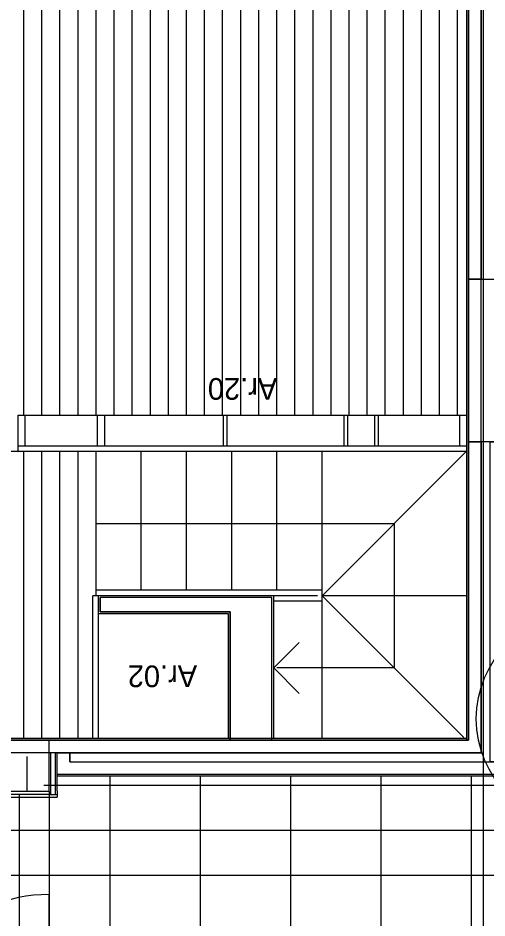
# Model space of a CAD drawing. Extents: x 1248 to 1356, y -443 to -224.
# Drawn here: x 1337.511 to 1340.106, y -239.409 to -234.424 of the extents above; entities that cross this region are included whole.
import ezdxf

# ---------------------------------------------------------------- set-up
doc = ezdxf.new("R2010")
doc.units = 0
for name, color, linetype in [('corte', 7, 'Continuous'), ('estereoctomias', 7, 'Continuous'), ('ind-pormenores', 7, 'Continuous'), ('Level 1', 7, 'Continuous'), ('Level 10', 7, 'Continuous'), ('Level 13', 7, 'Continuous'), ('Level 2', 7, 'Continuous'), ('Level 4', 7, 'Continuous'), ('Level 40', 7, 'Continuous'), ('revestimentos', 7, 'Continuous'), ('vermelhos-cont', 7, 'Continuous')]:
    doc.layers.add(name, color=color, linetype=linetype)

msp = doc.modelspace()

# ---------------------------------------------------------------- linework, layer by layer
at = {"layer": 'corte'}
for p, q in [((1340.0033, -238.424), (1340.0033, -232.264)), ((1340.0733, -236.7713), (1340.0733, -232.264)), ((1340.0733, -238.494), (1340.0733, -236.7713)), ((1340.0033, -238.424), (1336.8183, -238.424)), ((1337.7983, -238.494), (1340.0733, -238.494)), ((1337.7983, -238.544), (1341.234, -238.544)), ((1341.339, -238.614), (1337.7283, -238.614))]:
    msp.add_line(p, q, dxfattribs=at)
msp.add_lwpolyline([(1340.0033, -235.8713), (1340.2333, -235.8713), (1340.2333, -236.7713), (1340.0033, -236.7713)], close=True, dxfattribs=at)
at = {"layer": 'estereoctomias'}
for points in [[(1340.0733, -232.264), (1340.0733, -235.8713), (1340.0033, -235.8713), (1340.0033, -232.264)], [(1340.0733, -236.7713), (1340.0733, -238.4784), (1340.0733, -238.494), (1336.8883, -238.494), (1336.8883, -238.709), (1336.8183, -238.709), (1336.8183, -238.424), (1340.0033, -238.424), (1340.0033, -236.7713)], [(1341.339, -238.424), (1341.339, -238.614), (1337.7283, -238.614), (1337.7283, -238.544), (1337.7283, -238.494), (1337.7983, -238.494), (1337.7983, -238.544), (1341.234, -238.544), (1341.234, -238.244), (1340.804, -238.244), (1340.804, -238.544), (1340.774, -238.544), (1340.774, -238.244), (1340.234, -238.244), (1340.234, -238.544), (1340.124, -238.544), (1340.124, -236.7713), (1340.234, -236.7713), (1340.234, -238.094), (1341.154, -238.094), (1341.154, -237.584), (1341.304, -237.584), (1341.304, -238.424)], [(1338.9158, -238.424), (1338.9158, -237.634), (1337.9658, -237.634), (1337.9658, -237.714), (1338.6858, -237.714), (1338.6858, -238.424)]]:
    msp.add_lwpolyline(points, close=True, dxfattribs=at)
at = {"layer": 'ind-pormenores'}
msp.add_circle((1340.6308, -238.3059), 0.5842, dxfattribs=at)
at = {"layer": 'Level 1'}
for p, q in [((1340.0033, -232.264), (1340.0033, -238.424)), ((1337.9658, -237.714), (1337.9658, -237.634)), ((1338.9158, -237.634), (1337.9658, -237.634)), ((1338.9158, -238.424), (1338.9158, -237.634)), ((1338.6858, -237.714), (1337.9658, -237.714)), ((1338.6858, -238.424), (1338.6858, -237.714)), ((1337.7283, -238.494), (1336.8883, -238.494)), ((1337.7283, -238.614), (1337.7283, -238.494)), ((1337.7983, -238.544), (1337.7983, -238.494))]:
    msp.add_line(p, q, dxfattribs=at)
at = {"layer": 'Level 10'}
for p, q in [((1337.5433, -236.624), (1337.5433, -232.274)), ((1337.6433, -236.624), (1337.6433, -232.274)), ((1337.7433, -236.624), (1337.7433, -232.274)), ((1337.8433, -236.624), (1337.8433, -232.274)), ((1337.9433, -236.624), (1337.9433, -232.274)), ((1338.0433, -236.624), (1338.0433, -232.274)), ((1338.1433, -236.624), (1338.1433, -232.274)), ((1338.2433, -236.624), (1338.2433, -232.274)), ((1338.3433, -236.624), (1338.3433, -232.274)), ((1338.4433, -236.624), (1338.4433, -232.274)), ((1338.5433, -236.624), (1338.5433, -232.274)), ((1338.6433, -236.624), (1338.6433, -232.274)), ((1338.7433, -236.624), (1338.7433, -232.274)), ((1338.8433, -236.624), (1338.8433, -232.274)), ((1338.9433, -236.624), (1338.9433, -232.274)), ((1339.0433, -236.624), (1339.0433, -232.274)), ((1339.1433, -236.624), (1339.1433, -232.274)), ((1339.2433, -236.624), (1339.2433, -232.274)), ((1339.3433, -236.624), (1339.3433, -232.274)), ((1339.4433, -236.624), (1339.4433, -232.274)), ((1339.5433, -236.624), (1339.5433, -232.274)), ((1339.6433, -236.624), (1339.6433, -232.274)), ((1339.7433, -236.624), (1339.7433, -232.274)), ((1339.8433, -236.624), (1339.8433, -232.274)), ((1339.9433, -236.624), (1339.9433, -232.274)), ((1337.5433, -238.409), (1337.5433, -236.824)), ((1337.6433, -238.409), (1337.6433, -236.824)), ((1337.7433, -238.409), (1337.7433, -236.824)), ((1337.8433, -238.409), (1337.8433, -236.824)), ((1338.0183, -238.624), (1338.0183, -240.224)), ((1338.5183, -238.624), (1338.5183, -240.224)), ((1339.0183, -238.624), (1339.0183, -240.224)), ((1339.5183, -238.624), (1339.5183, -240.224)), ((1340.0183, -238.624), (1340.0183, -240.224)), ((1337.6533, -238.674), (1341.274, -238.674)), ((1337.5183, -238.724), (1337.5183, -240.124)), ((1348.9433, -238.924), (1315.7644, -238.924)), ((1347.9933, -239.174), (1315.7633, -239.174))]:
    msp.add_line(p, q, dxfattribs=at)
at = {"layer": 'Level 13'}
for p, q in [((1337.5113, -236.824), (1337.5113, -236.624)), ((1337.5113, -236.624), (1339.9933, -236.624)), ((1337.5513, -236.794), (1337.5513, -236.624)), ((1337.9513, -236.794), (1337.9513, -236.624)), ((1337.9913, -236.794), (1337.9913, -236.624)), ((1338.6486, -236.794), (1338.6486, -236.624)), ((1338.6686, -236.794), (1338.6686, -236.624)), ((1339.3159, -236.794), (1339.3159, -236.624)), ((1339.3359, -236.794), (1339.3359, -236.624)), ((1339.4859, -236.794), (1339.4859, -236.624)), ((1339.5059, -236.794), (1339.5059, -236.624)), ((1339.9533, -236.624), (1339.9533, -236.794)), ((1337.5113, -236.794), (1339.9933, -236.794)), ((1337.5113, -236.824), (1339.9933, -236.824)), ((1337.5113, -236.824), (1339.9933, -236.824)), ((1337.5113, -236.824), (1339.9933, -236.824)), ((1337.9398, -236.824), (1339.9933, -236.824)), ((1337.9258, -238.414), (1337.9258, -237.624)), ((1337.9558, -237.624), (1337.9258, -237.624)), ((1337.9733, -237.624), (1337.9433, -237.624)), ((1337.9558, -238.414), (1337.9558, -237.624)), ((1337.6833, -238.709), (1337.6833, -238.494)), ((1337.6933, -238.724), (1337.6933, -238.494)), ((1337.7183, -238.724), (1337.7183, -238.494)), ((1337.7283, -238.704), (1337.7283, -238.614)), ((1337.6833, -238.709), (1336.7783, -238.709)), ((1337.6833, -238.724), (1336.8183, -238.724)), ((1337.6833, -238.724), (1336.8183, -238.724)), ((1337.6833, -238.724), (1336.8283, -238.724)), ((1337.6833, -238.709), (1337.6833, -238.724)), ((1337.6833, -238.724), (1337.6833, -238.739)), ((1337.6833, -238.724), (1337.7283, -238.724)), ((1337.7283, -238.704), (1337.7283, -238.724)), ((1337.7283, -238.724), (1337.7283, -238.739)), ((1337.6833, -238.739), (1337.7283, -238.739))]:
    msp.add_line(p, q, dxfattribs=at)
at = {"layer": 'Level 2'}
for p, q in [((1337.9433, -237.624), (1337.9433, -236.824)), ((1337.9433, -237.624), (1337.9433, -236.824)), ((1338.1933, -237.594), (1338.1933, -236.824)), ((1338.4433, -237.594), (1338.4433, -236.824)), ((1338.6933, -237.594), (1338.6933, -236.824)), ((1338.9433, -237.594), (1338.9433, -236.824)), ((1339.1933, -237.594), (1339.1933, -236.824)), ((1339.1933, -237.624), (1339.9933, -236.824)), ((1337.9433, -237.224), (1339.5933, -237.224)), ((1339.5933, -238.024), (1339.5933, -237.224)), ((1339.1933, -237.594), (1337.9433, -237.594)), ((1339.1674, -237.624), (1337.9433, -237.624)), ((1339.1933, -237.654), (1339.1933, -237.594)), ((1339.9933, -237.624), (1339.1933, -237.624)), ((1339.1933, -237.624), (1339.9783, -238.409)), ((1339.1933, -237.654), (1338.9258, -237.654)), ((1339.1933, -237.654), (1338.9258, -237.654)), ((1339.1933, -238.409), (1339.1933, -237.654)), ((1339.0672, -237.8826), (1338.9258, -238.024)), ((1339.0672, -238.1654), (1338.9258, -238.024)), ((1339.5933, -238.024), (1338.9433, -238.024))]:
    msp.add_line(p, q, dxfattribs=at)
at = {"layer": 'Level 4'}
for p, q in [((1336.6933, -236.824), (1337.5113, -236.824)), ((1337.6833, -238.494), (1337.6833, -238.424)), ((1337.5608, -238.514), (1337.5608, -238.709)), ((1337.6833, -238.724), (1337.6833, -239.5941)), ((1335.9783, -238.739), (1337.6833, -238.739)), ((1337.6833, -240.124), (1337.6833, -239.279))]:
    msp.add_line(p, q, dxfattribs=at)
msp.add_arc((1337.6833, -240.124), 0.845, 90, 180, dxfattribs=at)
msp.add_ellipse((1337.6633, -238.739), major_axis=(-0.8551, 0), ratio=0.999998, start_param=0, end_param=1.570796, dxfattribs=at)
at = {"layer": 'revestimentos'}
for p, q in [((1339.9933, -232.274), (1339.9933, -238.424)), ((1337.9558, -237.724), (1337.9558, -237.624)), ((1338.9258, -238.414), (1338.9258, -237.624)), ((1338.6758, -237.724), (1337.9558, -237.724)), ((1338.6758, -238.414), (1338.6758, -237.724)), ((1339.9933, -238.414), (1336.8383, -238.414)), ((1339.9933, -238.414), (1338.9258, -238.414)), ((1341.329, -238.624), (1337.7283, -238.624))]:
    msp.add_line(p, q, dxfattribs=at)
at = {"layer": 'vermelhos-cont'}
msp.add_line((1340.084, -229.6198), (1340.084, -250.7923), dxfattribs=at)

# ---------------------------------------------------------------- texts
at = {"layer": 'Level 40'}
for s, p in [('Ar.20', (1338.9452, -236.4183)), ('Ar.02', (1338.5021, -238.0102))]:
    msp.add_text(s, height=0.12, rotation=180, dxfattribs=at).set_placement(p)

doc.saveas('drawing.dxf')
